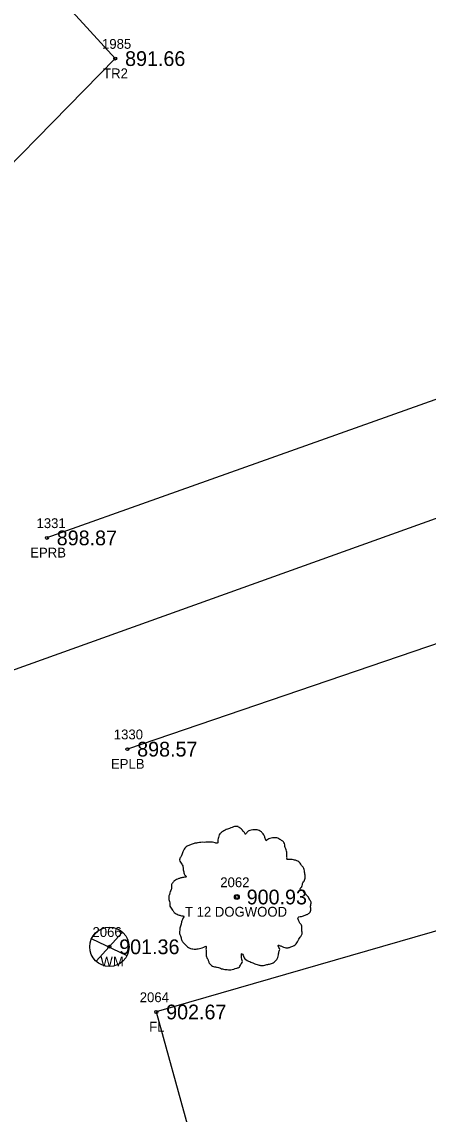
# Model space of a CAD drawing. Extents: x 1448136 to 1453623, y 1125056 to 1128842.
# Drawn here: x 1448885.5 to 1448926.9, y 1126836.9 to 1126948.2 of the extents above; entities that cross this region are included whole.
import ezdxf

# ---------------------------------------------------------------- set-up
doc = ezdxf.new("R2010")
doc.units = 0
for name, color, linetype in [('RD_EX_Fence_Other', 7, 'Continuous'), ('RD_EX_Fence_Other_txCode', 7, 'Continuous'), ('RD_EX_Road', 7, 'Continuous'), ('RD_EX_Road_txCode', 7, 'Continuous'), ('RD_EX_TX_Fence_Other_ELEV', 7, 'Continuous'), ('RD_EX_TX_Road_ELEV', 7, 'Continuous'), ('RD_EX_TX_UT_ELEV', 7, 'Continuous'), ('RD_EX_TX_VEG_ELEV', 7, 'Continuous'), ('RD_EX_UT', 7, 'Continuous'), ('RD_EX_UT_txCode', 7, 'Continuous'), ('RD_EX_VEG', 7, 'Continuous'), ('RD_EX_VEG_txCode', 7, 'Continuous'), ('RD_HC_Cl', 7, 'Continuous'), ('RD_SMD_Locator', 7, 'Continuous')]:
    doc.layers.add(name, color=color, linetype=linetype)

msp = doc.modelspace()

# ---------------------------------------------------------------- linework, layer by layer
at = {"layer": 'RD_EX_Fence_Other'}
msp.add_lwpolyline([(1448975.76, 1126805.4), (1449010.37, 1126832.06), (1449003.73, 1126876.29), (1448947.02, 1126861.17), (1448899.19, 1126847.35), (1448908.83, 1126812.34)], dxfattribs=at)
at = {"layer": 'RD_EX_Road'}
for points in [[(1449482.54, 1126860.68), (1449432.31, 1126877.02), (1449388.08, 1126891.1), (1449338.36, 1126907.04), (1449288.58, 1126921), (1449240.68, 1126932.6), (1449188.86, 1126940.12), (1449140.06, 1126943.48), (1449087.15, 1126942.31), (1449035.96, 1126936.97), (1449031.74, 1126936.28), (1449027.6, 1126937.81), (1449023.03, 1126937.4), (1448974.11, 1126927.16), (1448972.81, 1126925.93), (1448941.11, 1126916.24), (1448934.6, 1126912.22), (1448888.05, 1126895.64)], [(1449474.36, 1126838.35), (1449426.72, 1126853.6), (1449379.49, 1126868.74), (1449332.07, 1126883.87), (1449284.48, 1126897.19), (1449236.53, 1126909.1), (1449187.55, 1126916.77), (1449138.32, 1126919.77), (1449088.85, 1126918.94), (1449039.71, 1126913.91), (1448991.01, 1126903.73), (1448942.83, 1126890.02), (1448896.24, 1126874.12)]]:
    msp.add_lwpolyline(points, dxfattribs=at)
at = {"layer": 'RD_EX_UT'}
for p, q in [((1448893.05, 1126852.53), (1448895.72, 1126855.43)), ((1448892.57, 1126854.83), (1448896.2, 1126853.11))]:
    msp.add_line(p, q, dxfattribs=at)
msp.add_circle((1448894.41, 1126853.99), 2, dxfattribs=at)
at = {"layer": 'RD_EX_VEG'}
msp.add_lwpolyline([(1448868.01, 1126973.97), (1448895.01, 1126944.46), (1448877.49, 1126926.62), (1448865.85, 1126904.82)], dxfattribs=at)
for centre, radius in [((1448907.39, 1126859.06), 0.25), ((1448907.38, 1126859.04), 0.0001)]:
    msp.add_circle(centre, radius, dxfattribs=at)
for points in [[(1448907.52, 1126866.23), (1448907.22, 1126866.25), (1448906.9, 1126866.15), (1448906.65, 1126866.05), (1448906.42, 1126865.98), (1448906.2, 1126865.88), (1448905.9, 1126865.7), (1448905.67, 1126865.5), (1448905.55, 1126865.25), (1448905.5, 1126865.03), (1448905.45, 1126864.75), (1448905.45, 1126864.58), (1448905.32, 1126864.55), (1448905.17, 1126864.58), (1448904.92, 1126864.65), (1448904.67, 1126864.65), (1448904.42, 1126864.65), (1448904.07, 1126864.63), (1448903.72, 1126864.63), (1448903.45, 1126864.58), (1448903.12, 1126864.53), (1448902.75, 1126864.4), (1448902.4, 1126864.28), (1448902.1, 1126864.03), (1448901.85, 1126863.55), (1448901.72, 1126863.2), (1448901.57, 1126862.95), (1448901.72, 1126862.5), (1448901.9, 1126862.15), (1448901.92, 1126861.95), (1448902, 1126861.53), (1448902.1, 1126861.3), (1448902.22, 1126861.1), (1448902.15, 1126861.08), (1448901.77, 1126861.03), (1448901.47, 1126860.93), (1448901.05, 1126860.71), (1448900.82, 1126860.48), (1448900.72, 1126860.16), (1448900.7, 1126859.81), (1448900.6, 1126859.61), (1448900.53, 1126859.33), (1448900.5, 1126859.26), (1448900.45, 1126858.93), (1448900.55, 1126858.48), (1448900.58, 1126858.13), (1448900.7, 1126857.91), (1448900.85, 1126857.73), (1448901.02, 1126857.48), (1448901.42, 1126857.26), (1448901.75, 1126857.16), (1448901.95, 1126857.13), (1448901.77, 1126856.63), (1448901.72, 1126856.28), (1448901.6, 1126855.88), (1448901.6, 1126855.81), (1448901.55, 1126855.33), (1448901.7, 1126855.01), (1448901.77, 1126854.63), (1448901.95, 1126854.41), (1448902.22, 1126854.11), (1448902.55, 1126853.88), (1448903.05, 1126853.76), (1448903.45, 1126853.78), (1448904.02, 1126853.96), (1448904.27, 1126854.03), (1448904.25, 1126853.86), (1448904.27, 1126853.48), (1448904.27, 1126853.06), (1448904.42, 1126852.73), (1448904.52, 1126852.46), (1448904.67, 1126852.21), (1448905, 1126851.98), (1448905.4, 1126851.91), (1448905.82, 1126851.76), (1448906.27, 1126851.68), (1448906.77, 1126851.66), (1448907.37, 1126851.81), (1448907.65, 1126851.93), (1448907.75, 1126852.11), (1448907.95, 1126852.48), (1448907.9, 1126852.71), (1448907.92, 1126853.31), (1448908.02, 1126853.13), (1448908.2, 1126852.78), (1448908.7, 1126852.48), (1448909.1, 1126852.31), (1448909.57, 1126852.16), (1448909.87, 1126852.08), (1448910.35, 1126852.16), (1448910.72, 1126852.23), (1448911.1, 1126852.36), (1448911.4, 1126852.63), (1448911.57, 1126852.91), (1448911.62, 1126853.18), (1448911.7, 1126853.56), (1448911.75, 1126853.73)], [(1448911.75, 1126853.73), (1448911.67, 1126853.91), (1448911.62, 1126854.16), (1448911.7, 1126854.13), (1448911.87, 1126854.08), (1448912.15, 1126853.96), (1448912.37, 1126853.88), (1448912.69, 1126853.91), (1448912.97, 1126854.01), (1448913.42, 1126854.28), (1448913.69, 1126854.76), (1448913.97, 1126855.16), (1448914.04, 1126855.48), (1448913.99, 1126855.71), (1448913.97, 1126856.21), (1448913.77, 1126856.46), (1448913.72, 1126856.58), (1448913.62, 1126856.98), (1448913.69, 1126857.03), (1448913.97, 1126857.08), (1448914.34, 1126857.21), (1448914.62, 1126857.33), (1448914.84, 1126857.51), (1448914.92, 1126857.73), (1448914.89, 1126858.13), (1448914.94, 1126858.53), (1448914.87, 1126858.68), (1448914.77, 1126858.83), (1448914.69, 1126859.03), (1448914.54, 1126859.18), (1448914.44, 1126859.33), (1448914.34, 1126859.43), (1448914.22, 1126859.58), (1448914.04, 1126859.71), (1448913.89, 1126859.76), (1448913.84, 1126859.91), (1448913.99, 1126860.11), (1448914.04, 1126860.21), (1448914.07, 1126860.43), (1448914.29, 1126860.78), (1448914.34, 1126861.18), (1448914.29, 1126861.6), (1448914.24, 1126861.88), (1448914.09, 1126862.15), (1448913.89, 1126862.4), (1448913.77, 1126862.58), (1448913.59, 1126862.7), (1448913.27, 1126862.83), (1448913.02, 1126862.88), (1448912.67, 1126862.88), (1448912.47, 1126862.93), (1448912.49, 1126862.98), (1448912.49, 1126863.13), (1448912.49, 1126863.4), (1448912.42, 1126863.85), (1448912.27, 1126864.35), (1448912.27, 1126864.38), (1448912.17, 1126864.63), (1448911.95, 1126864.83), (1448911.77, 1126864.93), (1448911.57, 1126865.05), (1448911.32, 1126865.08), (1448911.02, 1126865.08), (1448910.75, 1126865.03), (1448910.55, 1126864.93), (1448910.37, 1126864.8), (1448910.3, 1126864.95), (1448910.2, 1126865.25), (1448910.15, 1126865.4), (1448910, 1126865.58), (1448909.77, 1126865.78), (1448909.32, 1126865.9), (1448908.7, 1126865.83), (1448908.4, 1126865.63), (1448908.25, 1126865.45), (1448908.2, 1126865.58), (1448908, 1126865.78), (1448907.9, 1126865.95), (1448907.72, 1126866.08), (1448907.57, 1126866.18), (1448907.47, 1126866.23)]]:
    msp.add_spline(points, degree=3, dxfattribs=at)
at = {"layer": 'RD_HC_Cl'}
msp.add_line((1448931, 1126898.83), (1448763.03, 1126838.55), dxfattribs=at)
at = {"layer": 'RD_SMD_Locator'}
for centre in [(1448895.01, 1126944.46), (1448888.05, 1126895.64), (1448896.24, 1126874.12), (1448907.39, 1126859.06), (1448894.41, 1126853.99), (1448899.19, 1126847.35)]:
    msp.add_circle(centre, 0.15, dxfattribs=at)

# ---------------------------------------------------------------- texts
at = {"layer": 'RD_EX_Fence_Other_txCode'}
for s, p in [('2064', (1448897.5, 1126848.35)), ('FL', (1448898.46, 1126845.35))]:
    msp.add_text(s, height=1, dxfattribs=at).set_placement(p)
at = {"layer": 'RD_EX_Road_txCode'}
for s, p in [('1331', (1448886.99, 1126896.64)), ('EPRB', (1448886.35, 1126893.64)), ('1330', (1448894.86, 1126875.12)), ('EPLB', (1448894.57, 1126872.12))]:
    msp.add_text(s, height=1, dxfattribs=at).set_placement(p)
at = {"layer": 'RD_EX_TX_Fence_Other_ELEV'}
msp.add_text('902.67', height=1.5, dxfattribs=at).set_placement((1448900.19, 1126846.6))
at = {"layer": 'RD_EX_TX_Road_ELEV'}
for s, p in [('898.87', (1448889.05, 1126894.89)), ('898.57', (1448897.24, 1126873.37))]:
    msp.add_text(s, height=1.5, dxfattribs=at).set_placement(p)
at = {"layer": 'RD_EX_TX_UT_ELEV'}
msp.add_text('901.36', height=1.5, dxfattribs=at).set_placement((1448895.41, 1126853.24))
at = {"layer": 'RD_EX_TX_VEG_ELEV'}
for s, p in [('891.66', (1448896.01, 1126943.71)), ('900.93', (1448908.39, 1126858.31))]:
    msp.add_text(s, height=1.5, dxfattribs=at).set_placement(p)
at = {"layer": 'RD_EX_UT_txCode'}
for s, p in [('2066', (1448892.69, 1126854.99)), ('WM', (1448893.5, 1126851.99))]:
    msp.add_text(s, height=1, dxfattribs=at).set_placement(p)
at = {"layer": 'RD_EX_VEG_txCode'}
for s, p in [('1985', (1448893.66, 1126945.46)), ('TR2', (1448893.77, 1126942.46)), ('2062', (1448905.7, 1126860.06)), ('T 12 DOGWOOD', (1448902.1, 1126857.06))]:
    msp.add_text(s, height=1, dxfattribs=at).set_placement(p)

doc.saveas('drawing.dxf')
